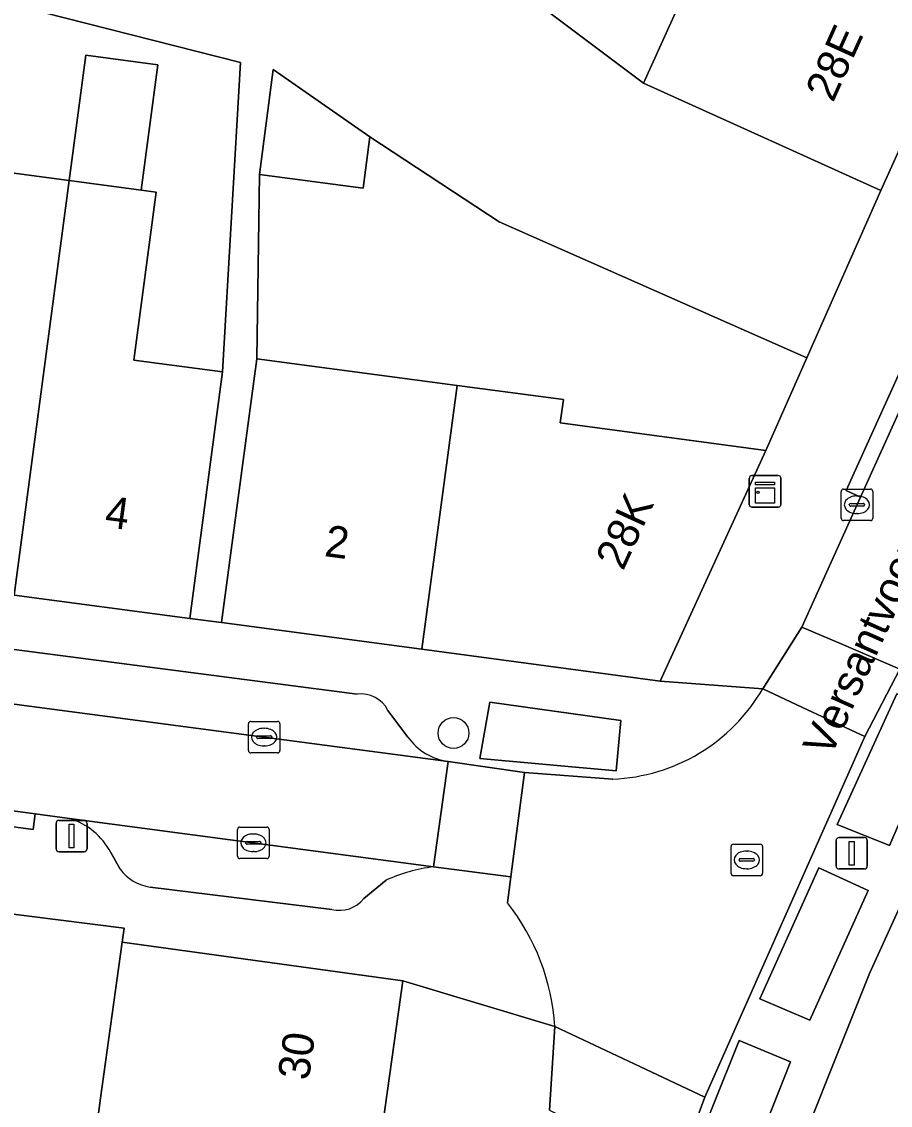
# Model space of a CAD drawing. Extents: x 161838 to 162344, y 381620 to 382160.
# Drawn here: x 162029.08 to 162056.65, y 381684.5 to 381718.88 of the extents above; entities that cross this region are included whole.
import ezdxf

# ---------------------------------------------------------------- set-up
doc = ezdxf.new("R2010")
doc.units = 0
for name, color, linetype in [('IMGEO_Boom', 7, 'Continuous'), ('IMGEO_Erf', 7, 'Continuous'), ('IMGEO_Kast', 7, 'Continuous'), ('IMGEO_Kolk', 7, 'Continuous'), ('IMGEO_Lichtmast', 7, 'Continuous'), ('IMGEO_Muur', 7, 'Continuous'), ('IMGEO_Openbare_ruimte_label', 7, 'Continuous'), ('IMGEO_Pand', 7, 'Continuous'), ('IMGEO_Pand_nummerreeks', 7, 'Continuous'), ('IMGEO_Parkeervlak_open', 7, 'Continuous'), ('IMGEO_Rijbaan_lokaal_open', 7, 'Continuous'), ('IMGEO_Rioolput', 7, 'Continuous'), ('IMGEO_Voetpad_open', 7, 'Continuous')]:
    doc.layers.add(name, color=color, linetype=linetype)

msp = doc.modelspace()

# ---------------------------------------------------------------- linework, layer by layer
at = {"layer": 'IMGEO_Boom'}
msp.add_circle((162042.788, 381696.309), 0.489, dxfattribs=at)
at = {"layer": 'IMGEO_Erf'}
for points in [[(162042.565, 381721.62), (162048.815, 381716.934), (162051.526, 381722.912)], [(162028.443, 381714.126), (162030.594, 381713.839), (162031.122, 381717.815), (162033.403, 381717.511), (162032.873, 381713.535), (162033.349, 381713.472), (162032.639, 381708.144), (162035.461, 381707.768), (162036.024, 381717.58), (162024.893, 381720.414)], [(162082.393, 381716.646), (162077.551, 381718.849), (162076.547, 381716.643), (162075.487, 381714.313), (162080.36, 381712.096), (162079.329, 381709.83), (162078.278, 381707.519), (162076.96, 381708.119), (162073.413, 381709.734), (162072.389, 381707.483), (162072.039, 381706.715), (162071.359, 381705.221), (162076.22, 381703.009), (162075.196, 381700.758), (162074.136, 381698.428), (162069.147, 381700.698), (162068.104, 381698.405), (162066.29, 381699.23), (162061.738, 381701.301), (162055.986, 381688.68), (162052.997, 381681.186)]]:
    msp.add_lwpolyline(points, dxfattribs=at)
for points in [[(162044.24, 381712.529), (162040.13, 381715.222), (162039.916, 381713.6), (162036.628, 381714.033), (162036.546, 381708.187), (162041.321, 381707.551), (162042.9, 381707.34), (162046.277, 381706.89), (162046.178, 381706.147), (162052.704, 381705.277), (162054.002, 381708.216)], [(162031.508, 381684.166), (162031.585, 381684.719), (162032.275, 381689.671), (162032.337, 381690.112), (162017.248, 381692.026), (162017.041, 381690.355), (162019.212, 381690.063), (162018.632, 381685.965), (162018.05, 381681.849), (162015.882, 381682.142), (162015.536, 381679.655), (162017.73, 381679.359), (162017.163, 381675.318), (162016.576, 381671.14), (162014.398, 381671.454), (162014.207, 381670.084), (162029.252, 381667.982), (162030.021, 381673.496), (162030.766, 381678.841)]]:
    msp.add_lwpolyline(points, close=True, dxfattribs=at)
at = {"layer": 'IMGEO_Kast'}
for p, q in [((162052.176, 381703.553), (162052.176, 381704.394)), ((162052.176, 381704.394), (162052.176, 381703.553)), ((162052.251, 381704.478), (162053.092, 381704.478)), ((162053.092, 381704.478), (162052.251, 381704.478)), ((162053.176, 381704.403), (162053.176, 381703.562)), ((162053.176, 381703.562), (162053.176, 381704.403)), ((162053.101, 381703.478), (162052.26, 381703.478)), ((162052.26, 381703.478), (162053.101, 381703.478))]:
    msp.add_line(p, q, dxfattribs=at)
for points in [[(162052.371, 381704.268), (162052.971, 381704.268), (162052.971, 381704.183), (162052.371, 381704.183), (162052.371, 381704.268)], [(162052.371, 381704.093), (162052.971, 381704.093), (162052.971, 381703.604), (162052.371, 381703.604), (162052.371, 381704.093)]]:
    msp.add_lwpolyline(points, dxfattribs=at)
msp.add_circle((162052.455, 381703.942), 0.0377, dxfattribs=at)
for centre, start, end in [((162052.254, 381704.4), 92.4484, 184.2845), ((162052.254, 381704.4), 92.4484, 184.2845), ((162053.098, 381704.4), 2.4484, 94.2845), ((162053.098, 381704.4), 2.4484, 94.2845), ((162052.254, 381703.556), 182.4484, 274.2845), ((162052.254, 381703.556), 182.4484, 274.2845), ((162053.098, 381703.556), 272.4484, 4.2845), ((162053.098, 381703.556), 272.4484, 4.2845)]:
    msp.add_arc(centre, 0.0779, start, end, dxfattribs=at)
at = {"layer": 'IMGEO_Kolk'}
for p, q in [((162055.09, 381703.125), (162055.09, 381703.977)), ((162055.165, 381704.051), (162056.017, 381704.051)), ((162056.091, 381703.977), (162056.091, 381703.125)), ((162055.349, 381703.545), (162055.349, 381703.557)), ((162055.392, 381703.594), (162055.79, 381703.594)), ((162055.578, 381703.831), (162055.603, 381703.831)), ((162055.833, 381703.557), (162055.833, 381703.545)), ((162055.787, 381703.508), (162055.389, 381703.508)), ((162055.601, 381703.271), (162055.576, 381703.271)), ((162056.017, 381703.051), (162055.165, 381703.051)), ((162036.355, 381696.679), (162037.207, 381696.679)), ((162036.28, 381695.753), (162036.28, 381696.605)), ((162036.768, 381696.459), (162036.793, 381696.459)), ((162037.281, 381696.605), (162037.281, 381695.753)), ((162036.539, 381696.173), (162036.539, 381696.185)), ((162036.977, 381696.136), (162036.579, 381696.136)), ((162036.582, 381696.222), (162036.98, 381696.222)), ((162037.023, 381696.185), (162037.023, 381696.173)), ((162037.207, 381695.679), (162036.355, 381695.679)), ((162036.791, 381695.899), (162036.766, 381695.899)), ((162035.936, 381692.399), (162035.936, 381693.251)), ((162036.011, 381693.325), (162036.863, 381693.325)), ((162036.937, 381693.251), (162036.937, 381692.399)), ((162036.424, 381693.105), (162036.449, 381693.105)), ((162036.195, 381692.819), (162036.195, 381692.831)), ((162036.633, 381692.782), (162036.235, 381692.782)), ((162036.238, 381692.868), (162036.636, 381692.868)), ((162036.447, 381692.545), (162036.422, 381692.545)), ((162036.679, 381692.831), (162036.679, 381692.819)), ((162036.863, 381692.325), (162036.011, 381692.325))]:
    msp.add_line(p, q, dxfattribs=at)
for points in [[(162055.09, 381703.125), (162055.09, 381703.977)], [(162055.165, 381704.051), (162056.017, 381704.051)], [(162056.091, 381703.977), (162056.091, 381703.125)], [(162056.017, 381703.051), (162055.165, 381703.051)], [(162036.355, 381696.679), (162037.207, 381696.679)], [(162036.28, 381695.753), (162036.28, 381696.605)], [(162037.281, 381696.605), (162037.281, 381695.753)], [(162037.207, 381695.679), (162036.355, 381695.679)], [(162035.936, 381692.399), (162035.936, 381693.251)], [(162036.011, 381693.325), (162036.863, 381693.325)], [(162036.937, 381693.251), (162036.937, 381692.399)], [(162036.863, 381692.325), (162036.011, 381692.325)]]:
    msp.add_lwpolyline(points, dxfattribs=at)
for centre, radius, start, end in [((162055.167, 381703.975), 0.0765, 91.552, 178.448), ((162055.167, 381703.975), 0.0765, 91.552, 178.448), ((162056.015, 381703.975), 0.0765, 1.552, 88.448), ((162056.015, 381703.975), 0.0765, 1.552, 88.448), ((162055.389, 381703.554), 0.0403, 85.8775, 175.7526), ((162055.386, 381703.544), 0.0366, 178.938, 274.7102), ((162055.79, 381703.551), 0.043, 264.8664, 352.4533), ((162055.794, 381703.556), 0.0386, 1.7309, 96.639), ((162055.167, 381703.127), 0.0765, 181.552, 268.448), ((162055.167, 381703.127), 0.0765, 181.552, 268.448), ((162056.015, 381703.127), 0.0765, 271.552, 358.448), ((162056.015, 381703.127), 0.0765, 271.552, 358.448), ((162036.357, 381696.603), 0.0765, 91.552, 178.448), ((162036.357, 381696.603), 0.0765, 91.552, 178.448), ((162037.205, 381696.603), 0.0765, 1.552, 88.448), ((162037.205, 381696.603), 0.0765, 1.552, 88.448), ((162036.579, 381696.182), 0.0403, 85.8775, 175.7526), ((162036.576, 381696.172), 0.0366, 178.938, 274.7102), ((162036.98, 381696.179), 0.043, 264.8664, 352.4533), ((162036.984, 381696.184), 0.0386, 1.7309, 96.639), ((162036.357, 381695.755), 0.0765, 181.552, 268.448), ((162036.357, 381695.755), 0.0765, 181.552, 268.448), ((162037.205, 381695.755), 0.0765, 271.552, 358.448), ((162037.205, 381695.755), 0.0765, 271.552, 358.448), ((162036.013, 381693.249), 0.0765, 91.552, 178.448), ((162036.013, 381693.249), 0.0765, 91.552, 178.448), ((162036.861, 381693.249), 0.0765, 1.552, 88.448), ((162036.861, 381693.249), 0.0765, 1.552, 88.448), ((162036.235, 381692.828), 0.0403, 85.8775, 175.7526), ((162036.232, 381692.818), 0.0366, 178.938, 274.7102), ((162036.636, 381692.825), 0.043, 264.8664, 352.4533), ((162036.64, 381692.83), 0.0386, 1.7309, 96.639), ((162036.013, 381692.401), 0.0765, 181.552, 268.448), ((162036.013, 381692.401), 0.0765, 181.552, 268.448), ((162036.861, 381692.401), 0.0765, 271.552, 358.448), ((162036.861, 381692.401), 0.0765, 271.552, 358.448)]:
    msp.add_arc(centre, radius, start, end, dxfattribs=at)
for centre, major_axis, ratio, start_param, end_param in [((162055.577, 381703.551), (-0.387, 0.002), 0.722429, 4.712389, 7.853982), ((162055.602, 381703.551), (-0.39, 0.002), 0.717154, 1.570796, 4.712389), ((162036.767, 381696.179), (-0.387, 0.002), 0.722429, 4.712389, 7.853982), ((162036.792, 381696.179), (-0.39, 0.002), 0.717154, 1.570796, 4.712389), ((162036.423, 381692.825), (-0.387, 0.002), 0.722429, 4.712389, 7.853982), ((162036.448, 381692.825), (-0.39, 0.002), 0.717154, 1.570796, 4.712389)]:
    msp.add_ellipse(centre, major_axis=major_axis, ratio=ratio, start_param=start_param, end_param=end_param, dxfattribs=at)
at = {"layer": 'IMGEO_Lichtmast'}
for p, q in [((162030.174, 381692.637), (162030.174, 381693.437)), ((162030.174, 381693.437), (162030.174, 381692.637)), ((162030.274, 381693.537), (162031.064, 381693.537)), ((162031.064, 381693.537), (162030.274, 381693.537)), ((162031.164, 381693.437), (162031.164, 381692.637)), ((162031.164, 381692.637), (162031.164, 381693.437)), ((162054.929, 381692.096), (162054.929, 381692.896)), ((162054.929, 381692.896), (162054.929, 381692.096)), ((162055.029, 381692.996), (162055.819, 381692.996)), ((162055.819, 381692.996), (162055.029, 381692.996)), ((162055.919, 381692.896), (162055.919, 381692.096)), ((162055.919, 381692.096), (162055.919, 381692.896)), ((162031.064, 381692.537), (162030.274, 381692.537)), ((162030.274, 381692.537), (162031.064, 381692.537)), ((162055.819, 381691.996), (162055.029, 381691.996)), ((162055.029, 381691.996), (162055.819, 381691.996))]:
    msp.add_line(p, q, dxfattribs=at)
for points in [[(162030.594, 381693.412), (162030.744, 381693.412), (162030.744, 381692.662), (162030.594, 381692.662), (162030.594, 381693.412)], [(162055.349, 381692.871), (162055.499, 381692.871), (162055.499, 381692.121), (162055.349, 381692.121), (162055.349, 381692.871)]]:
    msp.add_lwpolyline(points, dxfattribs=at)
for centre, start, end in [((162030.274, 381693.437), 90, 180), ((162030.274, 381693.437), 90, 180), ((162031.064, 381693.437), 0, 90), ((162031.064, 381693.437), 360, 90), ((162055.029, 381692.896), 90, 180), ((162055.029, 381692.896), 90, 180), ((162055.819, 381692.896), 0, 90), ((162055.819, 381692.896), 360, 90), ((162030.274, 381692.637), 180, 270), ((162030.274, 381692.637), 180, 270), ((162031.064, 381692.637), 270, 0), ((162031.064, 381692.637), 270, 0), ((162055.029, 381692.096), 180, 270), ((162055.029, 381692.096), 180, 270), ((162055.819, 381692.096), 270, 0), ((162055.819, 381692.096), 270, 0)]:
    msp.add_arc(centre, 0.1, start, end, dxfattribs=at)
at = {"layer": 'IMGEO_Muur'}
msp.add_lwpolyline([(162032.275, 381689.671), (162032.337, 381690.112), (162017.248, 381692.026)], dxfattribs=at)
at = {"layer": 'IMGEO_Pand'}
for points in [[(162056.347, 381713.524), (162059.046, 381719.488), (162054.491, 381721.55), (162051.526, 381722.912), (162048.815, 381716.934), (162051.793, 381715.586)], [(162030.594, 381713.839), (162032.873, 381713.535), (162033.403, 381717.511), (162031.122, 381717.815)], [(162040.13, 381715.222), (162037.066, 381717.36), (162036.628, 381714.033), (162039.916, 381713.6)], [(162030.594, 381713.839), (162028.443, 381714.126), (162028.006, 381714.184), (162027.301, 381708.895), (162024.596, 381709.256), (162023.552, 381701.393), (162028.849, 381700.688)], [(162035.461, 381707.768), (162032.639, 381708.144), (162033.349, 381713.472), (162032.873, 381713.535), (162030.594, 381713.839), (162028.849, 381700.688), (162034.419, 381699.947), (162035.079, 381704.904)], [(162042.9, 381707.34), (162041.321, 381707.551), (162036.546, 381708.187), (162036.094, 381704.795), (162035.43, 381699.815), (162041.781, 381698.968)], [(162042.9, 381707.34), (162041.781, 381698.968), (162049.351, 381697.959), (162052.704, 381705.277), (162046.178, 381706.147), (162046.277, 381706.89)], [(162031.508, 381684.166), (162040.411, 381682.922), (162041.184, 381688.441), (162032.275, 381689.671), (162031.585, 381684.719)]]:
    msp.add_lwpolyline(points, close=True, dxfattribs=at)
at = {"layer": 'IMGEO_Parkeervlak_open'}
for points in [[(162039.735, 381697.544), (162018.283, 381700.334)], [(162015.062, 381699.04), (162016.905, 381698.798), (162042.617, 381695.408)], [(162041.34, 381696.18), (162040.702, 381697.028)], [(162042.152, 381692.068), (162030.604, 381693.598)], [(162031.911, 381692.522), (162032.205, 381691.99)], [(162039.94, 381691.058), (162040.648, 381691.645)], [(162033.16, 381691.423), (162038.926, 381690.711)]]:
    msp.add_lwpolyline(points, dxfattribs=at)
for points in [[(162056.625, 381692.742), (162058.423, 381696.876), (162056.858, 381697.554), (162054.959, 381693.408)], [(162048.103, 381696.704), (162043.937, 381697.283), (162043.628, 381695.504), (162047.945, 381695.104)], [(162054.097, 381687.196), (162055.946, 381691.317), (162054.381, 381692.034), (162052.508, 381687.875)], [(162051.798, 381681.626), (162053.481, 381685.874), (162051.853, 381686.552), (162050.145, 381682.279)]]:
    msp.add_lwpolyline(points, close=True, dxfattribs=at)
for centre, radius, start, end in [((162039.855, 381696.605), 0.947, 26.5517, 97.2787), ((162042.879, 381697.283), 1.893, 215.6333, 262.0573), ((162029.949, 381691.471), 2.225, 28.1789, 72.8947), ((162033.373, 381692.869), 1.462, 216.9741, 261.6292), ((162042.999, 381686.171), 5.957, 98.1735, 113.2438), ((162039.162, 381691.675), 0.993, 256.2293, 321.5536)]:
    msp.add_arc(centre, radius, start, end, dxfattribs=at)
at = {"layer": 'IMGEO_Rijbaan_lokaal_open'}
for points in [[(162024.893, 381720.414), (162036.024, 381717.58), (162035.461, 381707.768), (162035.079, 381704.904), (162034.419, 381699.947), (162035.43, 381699.815), (162036.094, 381704.795), (162036.546, 381708.187), (162036.628, 381714.033), (162037.066, 381717.36), (162040.13, 381715.222), (162044.24, 381712.529), (162054.002, 381708.216), (162056.347, 381713.524), (162051.793, 381715.586), (162048.815, 381716.934), (162042.565, 381721.62)], [(162046, 381686.994), (162048.698, 381685.726), (162050.769, 381684.752), (162055.845, 381696.201), (162054.025, 381697.049), (162052.602, 381697.712)], [(162047.839, 381694.849), (162045.045, 381695.054), (162044.822, 381693.364), (162044.609, 381691.743), (162044.501, 381690.925)]]:
    msp.add_lwpolyline(points, dxfattribs=at)
for points in [[(162055.094, 381699.135), (162056.954, 381698.339), (162063.642, 381713.177), (162064.381, 381714.817), (162061.316, 381716.204), (162060.08, 381713.471), (162055.703, 381703.794), (162053.839, 381699.673)], [(162055.845, 381696.201), (162056.954, 381698.339), (162055.094, 381699.135), (162053.839, 381699.673), (162052.602, 381697.712), (162054.025, 381697.049)], [(162025.782, 381694.237), (162029.512, 381693.742), (162030.604, 381693.598), (162042.152, 381692.068), (162042.384, 381693.733), (162042.617, 381695.408), (162016.905, 381698.798), (162016.462, 381695.471)], [(162044.822, 381693.364), (162045.045, 381695.054), (162042.617, 381695.408), (162042.384, 381693.733), (162042.152, 381692.068), (162044.609, 381691.743)], [(162045.832, 381684.339), (162047.781, 381683.38), (162049.877, 381682.349), (162050.769, 381684.752), (162048.698, 381685.726), (162046, 381686.994)]]:
    msp.add_lwpolyline(points, close=True, dxfattribs=at)
for centre, radius, start, end in [((162047.622, 381700.603), 5.758, 272.1564, 329.863), ((162038.953, 381686.558), 7.06, 3.5397, 38.2068)]:
    msp.add_arc(centre, radius, start, end, dxfattribs=at)
at = {"layer": 'IMGEO_Rioolput'}
for p, q in [((162051.595, 381691.856), (162051.595, 381692.708)), ((162051.67, 381692.782), (162052.522, 381692.782)), ((162052.083, 381692.562), (162052.108, 381692.562)), ((162052.596, 381692.708), (162052.596, 381691.856)), ((162051.854, 381692.276), (162051.854, 381692.288)), ((162052.292, 381692.239), (162051.894, 381692.239)), ((162051.897, 381692.325), (162052.295, 381692.325)), ((162052.338, 381692.288), (162052.338, 381692.276)), ((162052.106, 381692.002), (162052.081, 381692.002)), ((162052.522, 381691.782), (162051.67, 381691.782))]:
    msp.add_line(p, q, dxfattribs=at)
for points in [[(162051.595, 381691.856), (162051.595, 381692.708)], [(162051.67, 381692.782), (162052.522, 381692.782)], [(162052.596, 381692.708), (162052.596, 381691.856)], [(162052.522, 381691.782), (162051.67, 381691.782)]]:
    msp.add_lwpolyline(points, dxfattribs=at)
for centre, radius, start, end in [((162051.672, 381692.706), 0.0765, 91.552, 178.448), ((162051.672, 381692.706), 0.0765, 91.552, 178.448), ((162052.52, 381692.706), 0.0765, 1.552, 88.448), ((162052.52, 381692.706), 0.0765, 1.552, 88.448), ((162051.894, 381692.285), 0.0403, 85.8775, 175.7526), ((162051.891, 381692.275), 0.0366, 178.938, 274.7102), ((162052.295, 381692.282), 0.043, 264.8664, 352.4533), ((162052.299, 381692.287), 0.0386, 1.7309, 96.639), ((162051.672, 381691.858), 0.0765, 181.552, 268.448), ((162051.672, 381691.858), 0.0765, 181.552, 268.448), ((162052.52, 381691.858), 0.0765, 271.552, 358.448), ((162052.52, 381691.858), 0.0765, 271.552, 358.448)]:
    msp.add_arc(centre, radius, start, end, dxfattribs=at)
for centre, major_axis, ratio, start_param, end_param in [((162052.082, 381692.282), (-0.387, 0.002), 0.722429, 4.712389, 7.853982), ((162052.107, 381692.282), (-0.39, 0.002), 0.717154, 1.570796, 4.712389)]:
    msp.add_ellipse(centre, major_axis=major_axis, ratio=ratio, start_param=start_param, end_param=end_param, dxfattribs=at)
at = {"layer": 'IMGEO_Voetpad_open'}
for points in [[(162071.683, 381741.12), (162069.369, 381742.199), (162067.005, 381736.977), (162064.483, 381731.405), (162061.89, 381725.676), (162059.528, 381720.458), (162059.046, 381719.488), (162056.347, 381713.524), (162054.002, 381708.216), (162052.704, 381705.277), (162049.351, 381697.959), (162052.602, 381697.712), (162053.839, 381699.673), (162055.703, 381703.794), (162055.249, 381704.002), (162059.626, 381713.679), (162060.08, 381713.471), (162061.316, 381716.204), (162062.449, 381718.709), (162062.541, 381718.913)], [(162056.954, 381698.339), (162055.845, 381696.201), (162050.769, 381684.752), (162049.877, 381682.349), (162050.145, 381682.279), (162051.853, 381686.552), (162053.481, 381685.874), (162051.798, 381681.626), (162052.997, 381681.186), (162055.986, 381688.68), (162061.738, 381701.301), (162063.841, 381705.924), (162065.894, 381710.438), (162067.969, 381714.998), (162070.06, 381719.595), (162072.147, 381724.183), (162074.208, 381728.716), (162076.306, 381733.328), (162078.267, 381737.638)], [(162052.602, 381697.712), (162049.351, 381697.959), (162041.781, 381698.968), (162035.43, 381699.815), (162034.419, 381699.947), (162028.849, 381700.688), (162023.552, 381701.393), (162018.578, 381702.055), (162009.676, 381703.239), (162004.764, 381703.893), (162000, 381704.527), (161999.589, 381704.582), (161994.25, 381705.292), (161989.039, 381705.985), (161987.777, 381706.147), (161956.476, 381710.172), (161955.308, 381710.322), (161949.883, 381711.029), (161944.702, 381711.705), (161939.487, 381712.385), (161934.405, 381713.048)], [(161955.123, 381700.39), (161986.324, 381696.353), (161987.561, 381696.193), (161992.899, 381695.471), (161998.113, 381694.765), (162000, 381694.51), (162003.254, 381694.07), (162008.529, 381693.356), (162012.746, 381692.786), (162012.629, 381691.911), (162014.938, 381691.603), (162015.256, 381691.555), (162016.395, 381691.381), (162016.489, 381692.122), (162017.248, 381692.026), (162032.337, 381690.112), (162032.275, 381689.671), (162041.184, 381688.441), (162046, 381686.994)], [(162018.283, 381700.334), (162039.735, 381697.544)], [(162040.702, 381697.028), (162041.34, 381696.18)], [(162042.617, 381695.408), (162045.045, 381695.054), (162047.839, 381694.849)], [(162030.604, 381693.598), (162029.512, 381693.742), (162029.445, 381693.247), (162025.724, 381693.74), (162025.782, 381694.237)], [(162032.205, 381691.99), (162031.911, 381692.522)], [(162044.501, 381690.925), (162044.609, 381691.743), (162042.152, 381692.068)], [(162040.648, 381691.645), (162039.94, 381691.058)], [(162038.926, 381690.711), (162033.16, 381691.423)], [(162045.832, 381684.339), (162046, 381686.994), (162041.184, 381688.441), (162040.411, 381682.922), (162039.661, 381677.574), (162038.913, 381672.236), (162038.143, 381666.74), (162037.94, 381665.172), (162038.451, 381665.101), (162036.767, 381653.483), (162035.189, 381642.607), (162038.836, 381642), (162039.032, 381643.481)]]:
    msp.add_lwpolyline(points, dxfattribs=at)
for points in [[(162055.703, 381703.794), (162060.08, 381713.471), (162059.626, 381713.679), (162055.249, 381704.002)], [(162058.423, 381696.876), (162056.625, 381692.742), (162054.959, 381693.408), (162056.858, 381697.554)], [(162043.937, 381697.283), (162048.103, 381696.704), (162047.945, 381695.104), (162043.628, 381695.504)], [(162025.782, 381694.237), (162025.724, 381693.74), (162029.445, 381693.247), (162029.512, 381693.742)], [(162055.946, 381691.317), (162054.097, 381687.196), (162052.508, 381687.875), (162054.381, 381692.034)]]:
    msp.add_lwpolyline(points, close=True, dxfattribs=at)
for centre, radius, start, end in [((162047.622, 381700.603), 5.758, 272.1564, 329.863), ((162039.855, 381696.605), 0.947, 26.5517, 97.2787), ((162042.879, 381697.283), 1.893, 215.6333, 262.0573), ((162029.949, 381691.471), 2.225, 28.1789, 72.8947), ((162033.373, 381692.869), 1.462, 216.9741, 261.6292), ((162042.999, 381686.171), 5.957, 98.1735, 113.2438), ((162039.162, 381691.675), 0.993, 256.2293, 321.5536), ((162038.953, 381686.558), 7.06, 3.5397, 38.2068)]:
    msp.add_arc(centre, radius, start, end, dxfattribs=at)

# ---------------------------------------------------------------- texts
at = {"layer": 'IMGEO_Openbare_ruimte_label'}
msp.add_text('Versantvoortstraat', height=1, rotation=65.8454, dxfattribs=at).set_placement((162054.755, 381695.505))
at = {"layer": 'IMGEO_Pand_nummerreeks'}
for s, rotation, p in [('28E', 65.6509, (162054.832, 381716.289)), ('28K', 65.3834, (162048.17, 381701.431)), ('4', 352.4198, (162031.694, 381702.851)), ('2', 352.4059, (162038.664, 381701.926)), ('30', 82.023, (162038.194, 381685.262))]:
    msp.add_text(s, height=1, rotation=rotation, dxfattribs=at).set_placement(p)

doc.saveas('drawing.dxf')
